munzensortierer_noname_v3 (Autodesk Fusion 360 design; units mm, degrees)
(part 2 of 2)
sketch "Skizze17" plane through (0, 0, 5.5) normal (0, 0, 1) x axis (1, 0, 0)
  line L1 (-47.8727, -14.1812) -> (-44.0075, -16.7301)
  line L2 (-31.8901, -15.0258) -> (-28.878, -11.5095)
  line L3 (33.1746, -11.9249) -> (28.5582, -12.2814)
  line L4 (43.8787, -23.8235) -> (42.948, -19.288)
  line L5 (-33.1746, 11.9249) -> (-28.5582, 12.2814)
  line L6 (-43.8787, 23.8235) -> (-42.948, 19.288)
  line L7 (11.9249, 33.1746) -> (12.2814, 28.5582)
  line L8 (23.8235, 43.8787) -> (19.288, 42.948)
  line L9 (-15.0258, 31.8901) -> (-11.5095, 28.878)
  line L10 (-14.1812, 47.8727) -> (-16.7301, 44.0075)
  line L11 (31.8901, 15.0258) -> (28.878, 11.5095)
  line L12 (47.8727, 14.1812) -> (44.0075, 16.7301)
  line L13 (15.0258, -31.8901) -> (11.5095, -28.878)
  line L14 (14.1812, -47.8727) -> (16.7301, -44.0075)
  line L15 (-23.8235, -43.8787) -> (-19.288, -42.948)
  line L16 (-11.9249, -33.1746) -> (-12.2814, -28.5582)
  arc A1 centre (-38.9151, -9.0081) radius 9.25 clockwise from (-31.8901, -15.0258) to (-44.0075, -16.7301)
  arc A2 centre (-39.8901, -2.0763) radius 14.5 clockwise from (-47.8727, -14.1812) to (-28.878, -11.5095)
  arc A3 centre (33.8868, -21.1475) radius 9.25 clockwise from (33.1746, -11.9249) to (42.948, -19.288)
  arc A4 centre (29.6747, -26.7384) radius 14.5 clockwise from (43.8787, -23.8235) to (28.5582, -12.2814)
  arc A5 centre (-29.6747, 26.7384) radius 14.5 clockwise from (-43.8787, 23.8235) to (-28.5582, 12.2814)
  arc A6 centre (-33.8868, 21.1475) radius 9.25 clockwise from (-33.1746, 11.9249) to (-42.948, 19.288)
  arc A7 centre (26.7384, 29.6747) radius 14.5 clockwise from (23.8235, 43.8787) to (12.2814, 28.5582)
  arc A8 centre (21.1475, 33.8868) radius 9.25 clockwise from (11.9249, 33.1746) to (19.288, 42.948)
  circle C1 centre (0, 0) radius 12.75
  arc A9 centre (0, 0) radius 59.0691 clockwise from (-58.9676, -3.4614) to (-59.0542, -1.3241)
  arc A10 centre (-58.8811, -4.7084) radius 1.25 clockwise from (-58.9676, -3.4614) to (-58.7683, -5.9533)
  arc A11 centre (0, 0) radius 59.0691 clockwise from (-58.5142, -8.0773) to (-58.7683, -5.9533)
  arc A12 centre (-58.3302, -9.3137) radius 1.25 clockwise from (-58.5142, -8.0773) to (-58.1201, -10.5459)
  arc A13 centre (0, 0) radius 59.0691 clockwise from (-57.7001, -12.6434) to (-58.1201, -10.5459)
  arc A14 centre (-57.4197, -13.8615) radius 1.25 clockwise from (-57.7001, -12.6434) to (-57.1135, -15.0734)
  arc A15 centre (0, 0) radius 59.0691 clockwise from (-56.5303, -17.1315) to (-57.1135, -15.0734)
  arc A16 centre (-56.1551, -18.3239) radius 1.25 clockwise from (-56.5303, -17.1315) to (-55.7548, -19.508)
  arc A17 centre (0, 0) radius 59.0691 clockwise from (-55.0119, -21.514) to (-55.7548, -19.508)
  arc A18 centre (-54.5443, -22.6732) radius 1.25 clockwise from (-55.0119, -21.514) to (-54.0523, -23.8224)
  arc A19 centre (0, 0) radius 59.0691 clockwise from (-53.1543, -25.7638) to (-54.0523, -23.8224)
  arc A20 centre (-52.5972, -26.8829) radius 1.25 clockwise from (-53.1543, -25.7638) to (-52.0166, -27.9898)
  arc A21 centre (0, 0) radius 59.0691 clockwise from (-50.9691, -29.8549) to (-52.0166, -27.9898)
  arc A22 centre (-50.3259, -30.9267) radius 1.25 clockwise from (-50.9691, -29.8549) to (-49.6602, -31.9847)
  arc A23 centre (0, 0) radius 59.0691 clockwise from (-48.4695, -33.7618) to (-49.6602, -31.9847)
  arc A24 centre (-47.7443, -34.7799) radius 1.25 clockwise from (-48.4695, -33.7618) to (-46.9976, -35.7824)
  arc A25 centre (0, 0) radius 59.0691 clockwise from (-45.6712, -37.4606) to (-46.9976, -35.7824)
  arc A26 centre (-44.8683, -38.4187) radius 1.25 clockwise from (-45.6712, -37.4606) to (-44.0453, -39.3595)
  arc A27 centre (0, 0) radius 59.0691 clockwise from (-42.5913, -40.9285) to (-44.0453, -39.3595)
  arc A28 centre (-41.7157, -41.8206) radius 1.25 clockwise from (-42.5913, -40.9285) to (-40.8214, -42.6939)
  arc A29 centre (0, 0) radius 59.0691 clockwise from (-39.2488, -44.144) to (-40.8214, -42.6939)
  arc A30 centre (-38.3059, -44.9646) radius 1.25 clockwise from (-39.2488, -44.144) to (-37.3458, -45.7651)
  arc A31 centre (0, 0) radius 59.0691 clockwise from (-35.6643, -47.0873) to (-37.3458, -45.7651)
  arc A32 centre (-34.6599, -47.8314) radius 1.25 clockwise from (-35.6643, -47.0873) to (-33.64, -48.5542)
  arc A33 centre (0, 0) radius 59.0691 clockwise from (-31.8599, -49.7403) to (-33.64, -48.5542)
  arc A34 centre (-30.8003, -50.4034) radius 1.25 clockwise from (-31.8599, -49.7403) to (-29.7268, -51.0438)
  arc A35 centre (0, 0) radius 59.0691 clockwise from (-27.8591, -52.0867) to (-29.7268, -51.0438)
  arc A36 centre (-26.7507, -52.6646) radius 1.25 clockwise from (-27.8591, -52.0867) to (-25.6303, -53.2188)
  arc A37 centre (0, 0) radius 59.0691 clockwise from (-23.6866, -54.112) to (-25.6303, -53.2188)
  arc A38 centre (-22.5362, -54.6011) radius 1.25 clockwise from (-23.6866, -54.112) to (-21.3758, -55.0657)
  arc A39 centre (0, 0) radius 59.0691 clockwise from (-19.368, -55.8036) to (-21.3758, -55.0657)
  arc A40 centre (-18.1828, -56.2009) radius 1.25 clockwise from (-19.368, -55.8036) to (-16.9895, -56.5731)
  arc A41 centre (0, 0) radius 59.0691 clockwise from (-14.93, -57.1511) to (-16.9895, -56.5731)
  arc A42 centre (-13.7173, -57.4543) radius 1.25 clockwise from (-14.93, -57.1511) to (-12.4985, -57.7317)
  arc A43 centre (0, 0) radius 59.0691 clockwise from (-10.3999, -58.1464) to (-12.4985, -57.7317)
  arc A44 centre (-9.1672, -58.3534) radius 1.25 clockwise from (-10.3999, -58.1464) to (-7.9304, -58.5343)
  arc A45 centre (0, 0) radius 59.0691 clockwise from (-5.8058, -58.7831) to (-7.9304, -58.5343)
  arc A46 centre (-4.5606, -58.8928) radius 1.25 clockwise from (-5.8058, -58.7831) to (-3.3134, -58.9761)
  arc A47 centre (0, 0) radius 59.0691 clockwise from (-1.1758, -59.0574) to (-3.3134, -58.9761)
  arc A48 centre (0.0741, -59.069) radius 1.25 clockwise from (-1.1758, -59.0574) to (1.3241, -59.0542)
  arc A49 centre (0, 0) radius 59.0691 clockwise from (3.4614, -58.9676) to (1.3241, -59.0542)
  arc A50 centre (4.7084, -58.8811) radius 1.25 clockwise from (3.4614, -58.9676) to (5.9533, -58.7683)
  arc A51 centre (0, 0) radius 59.0691 clockwise from (8.0773, -58.5142) to (5.9533, -58.7683)
  arc A52 centre (9.3137, -58.3302) radius 1.25 clockwise from (8.0773, -58.5142) to (10.5459, -58.1201)
  arc A53 centre (0, 0) radius 59.0691 clockwise from (12.6434, -57.7001) to (10.5459, -58.1201)
  arc A54 centre (13.8615, -57.4197) radius 1.25 clockwise from (12.6434, -57.7001) to (15.0734, -57.1135)
  arc A55 centre (0, 0) radius 59.0691 clockwise from (17.1315, -56.5303) to (15.0734, -57.1135)
  arc A56 centre (18.3239, -56.1551) radius 1.25 clockwise from (17.1315, -56.5303) to (19.508, -55.7548)
  arc A57 centre (0, 0) radius 59.0691 clockwise from (21.514, -55.0119) to (19.508, -55.7548)
  arc A58 centre (22.6732, -54.5443) radius 1.25 clockwise from (21.514, -55.0119) to (23.8224, -54.0523)
  arc A59 centre (0, 0) radius 59.0691 clockwise from (25.7638, -53.1543) to (23.8224, -54.0523)
  arc A60 centre (26.8829, -52.5972) radius 1.25 clockwise from (25.7638, -53.1543) to (27.9898, -52.0166)
  arc A61 centre (0, 0) radius 59.0691 clockwise from (29.8549, -50.9691) to (27.9898, -52.0166)
  arc A62 centre (30.9267, -50.3259) radius 1.25 clockwise from (29.8549, -50.9691) to (31.9847, -49.6602)
  arc A63 centre (0, 0) radius 59.0691 clockwise from (33.7618, -48.4695) to (31.9847, -49.6602)
  arc A64 centre (34.7799, -47.7443) radius 1.25 clockwise from (33.7618, -48.4695) to (35.7824, -46.9976)
  arc A65 centre (0, 0) radius 59.0691 clockwise from (37.4606, -45.6712) to (35.7824, -46.9976)
  arc A66 centre (38.4187, -44.8683) radius 1.25 clockwise from (37.4606, -45.6712) to (39.3595, -44.0453)
  arc A67 centre (0, 0) radius 59.0691 clockwise from (40.9285, -42.5913) to (39.3595, -44.0453)
  arc A68 centre (41.8206, -41.7157) radius 1.25 clockwise from (40.9285, -42.5913) to (42.6939, -40.8214)
  arc A69 centre (0, 0) radius 59.0691 clockwise from (44.144, -39.2488) to (42.6939, -40.8214)
  arc A70 centre (44.9646, -38.3059) radius 1.25 clockwise from (44.144, -39.2488) to (45.7651, -37.3458)
  arc A71 centre (0, 0) radius 59.0691 clockwise from (47.0873, -35.6643) to (45.7651, -37.3458)
  arc A72 centre (47.8314, -34.6599) radius 1.25 clockwise from (47.0873, -35.6643) to (48.5542, -33.64)
  arc A73 centre (0, 0) radius 59.0691 clockwise from (49.7403, -31.8599) to (48.5542, -33.64)
  arc A74 centre (50.4034, -30.8003) radius 1.25 clockwise from (49.7403, -31.8599) to (51.0438, -29.7268)
  arc A75 centre (0, 0) radius 59.0691 clockwise from (52.0867, -27.8591) to (51.0438, -29.7268)
  arc A76 centre (52.6646, -26.7507) radius 1.25 clockwise from (52.0867, -27.8591) to (53.2188, -25.6303)
  arc A77 centre (0, 0) radius 59.0691 clockwise from (54.112, -23.6866) to (53.2188, -25.6303)
  arc A78 centre (54.6011, -22.5362) radius 1.25 clockwise from (54.112, -23.6866) to (55.0657, -21.3758)
  arc A79 centre (0, 0) radius 59.0691 clockwise from (55.8036, -19.368) to (55.0657, -21.3758)
  arc A80 centre (56.2009, -18.1828) radius 1.25 clockwise from (55.8036, -19.368) to (56.5731, -16.9895)
  arc A81 centre (0, 0) radius 59.0691 clockwise from (57.1511, -14.93) to (56.5731, -16.9895)
  arc A82 centre (57.4543, -13.7173) radius 1.25 clockwise from (57.1511, -14.93) to (57.7317, -12.4985)
  arc A83 centre (0, 0) radius 59.0691 clockwise from (58.1464, -10.3999) to (57.7317, -12.4985)
  arc A84 centre (58.3534, -9.1672) radius 1.25 clockwise from (58.1464, -10.3999) to (58.5343, -7.9304)
  arc A85 centre (0, 0) radius 59.0691 clockwise from (58.7831, -5.8058) to (58.5343, -7.9304)
  arc A86 centre (58.8928, -4.5606) radius 1.25 clockwise from (58.7831, -5.8058) to (58.9761, -3.3134)
  arc A87 centre (0, 0) radius 59.0691 clockwise from (59.0574, -1.1758) to (58.9761, -3.3134)
  arc A88 centre (59.069, 0.0741) radius 1.25 clockwise from (59.0574, -1.1758) to (59.0542, 1.3241)
  arc A89 centre (0, 0) radius 59.0691 clockwise from (58.9676, 3.4614) to (59.0542, 1.3241)
  arc A90 centre (58.8811, 4.7084) radius 1.25 clockwise from (58.9676, 3.4614) to (58.7683, 5.9533)
  arc A91 centre (0, 0) radius 59.0691 clockwise from (58.5142, 8.0773) to (58.7683, 5.9533)
  arc A92 centre (58.3302, 9.3137) radius 1.25 clockwise from (58.5142, 8.0773) to (58.1201, 10.5459)
  arc A93 centre (0, 0) radius 59.0691 clockwise from (57.7001, 12.6434) to (58.1201, 10.5459)
  arc A94 centre (57.4197, 13.8615) radius 1.25 clockwise from (57.7001, 12.6434) to (57.1135, 15.0734)
  arc A95 centre (0, 0) radius 59.0691 clockwise from (56.5303, 17.1315) to (57.1135, 15.0734)
  arc A96 centre (56.1551, 18.3239) radius 1.25 clockwise from (56.5303, 17.1315) to (55.7548, 19.508)
  arc A97 centre (0, 0) radius 59.0691 clockwise from (55.0119, 21.514) to (55.7548, 19.508)
  arc A98 centre (54.5443, 22.6732) radius 1.25 clockwise from (55.0119, 21.514) to (54.0523, 23.8224)
  arc A99 centre (0, 0) radius 59.0691 clockwise from (53.1543, 25.7638) to (54.0523, 23.8224)
  arc A100 centre (52.5972, 26.8829) radius 1.25 clockwise from (53.1543, 25.7638) to (52.0166, 27.9898)
  arc A101 centre (0, 0) radius 59.0691 clockwise from (50.9691, 29.8549) to (52.0166, 27.9898)
  arc A102 centre (50.3259, 30.9267) radius 1.25 clockwise from (50.9691, 29.8549) to (49.6602, 31.9847)
  arc A103 centre (0, 0) radius 59.0691 clockwise from (48.4695, 33.7618) to (49.6602, 31.9847)
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  point P1 (0, 0)
  point P291 (0, 0)
  point P292 (0, 0)
  coincident P1 P291
  coincident P1 P292
extrude "Extrusion22" cut sketch "Skizze17" against normal blind 1
delete_face "Fläche löschen5"
delete_face "Fläche löschen6"
delete_face "Fläche löschen7"
delete_face "Fläche löschen8"
delete_face "Fläche löschen9"
delete_face "Fläche löschen10"
delete_face "Fläche löschen11"
delete_face "Fläche löschen12"
delete_face "Fläche löschen13"
delete_face "Fläche löschen14"
delete_face "Fläche löschen15"
delete_face "Fläche löschen16"
delete_face "Fläche löschen17"
delete_face "Fläche löschen18"
delete_face "Fläche löschen19"
delete_face "Fläche löschen20"
delete_face "Fläche löschen21"
sketch "Skizze18" plane through (0, 0, 65.6) normal (0, 0, 1) x axis (1, 0, 0)
  circle C1 centre (0, -39.9441) radius 32.1523
  circle C2 centre (0, -39.9441) radius 32.7523
extrude "Extrusion23" cut sketch "Skizze18" against normal blind 50
sketch "Skizze19" plane through (0, 0, 5.6) normal (0, 0, -1) x axis (-1, 0, 0)
  line L1 (8, -7) -> (12.9832, -7)
  line L2 (6, 6) -> (6, -5)
  line L3 (6.866, 6.5) -> (6, 6)
  line L4 (6.866, 7.5) -> (6.866, 6.5)
  line L5 (5.283, 10.1145) -> (6.3981, 8.7856)
  line L6 (4.4, 4.2486) -> (4.4, 9.7931)
  line L7 (3.1368, -5.4838) -> (3.2712, -4.9445)
  line L8 (-1.1962, -7) -> (1.1962, -7)
  line L9 (-3.2712, -4.9445) -> (-3.1368, -5.4838)
  line L10 (-4.4, 9.7931) -> (-4.4, 4.2486)
  line L11 (-6.3981, 8.7856) -> (-5.283, 10.1145)
  line L12 (-6.866, 6.5) -> (-6.866, 7.5)
  line L13 (-6, 6) -> (-6.866, 6.5)
  line L14 (-6, -5) -> (-6, 6)
  line L15 (-12.9832, -7) -> (-8, -7)
  line L16 (-14.75, 18.2945) -> (-14.75, 0)
  line L17 (-18.3545, -42.2598) -> (-23.3152, -2.9416)
  line L18 (23.3152, -2.9416) -> (18.3545, -42.2598)
  line L19 (14.75, 0) -> (14.75, 18.2945)
  line L20 (0, -39.9441) -> (7, -39.9441)
  line L21 (7, -25.6441) -> (0, -25.6441)
  line L22 (7, -54.2441) -> (0, -54.2441)
  circle C1 centre (0, -39.9441) radius 13.5
  arc A1 centre (8, -5) radius 2 clockwise from (8, -7) to (6, -5)
  arc A2 centre (4.866, 7.5) radius 2 clockwise from (6.3981, 8.7856) to (6.866, 7.5)
  arc A3 centre (4.9, 9.7931) radius 0.5 clockwise from (4.4, 9.7931) to (5.283, 10.1145)
  arc A4 centre (-33.6, 4.2486) radius 38 clockwise from (4.4, 4.2486) to (3.2712, -4.9445)
  arc A5 centre (1.1962, -5) radius 2 clockwise from (3.1368, -5.4838) to (1.1962, -7)
  arc A6 centre (-1.1962, -5) radius 2 clockwise from (-1.1962, -7) to (-3.1368, -5.4838)
  arc A7 centre (33.6, 4.2486) radius 38 clockwise from (-3.2712, -4.9445) to (-4.4, 4.2486)
  arc A8 centre (-4.9, 9.7931) radius 0.5 clockwise from (-5.283, 10.1145) to (-4.4, 9.7931)
  arc A9 centre (-4.866, 7.5) radius 2 clockwise from (-6.866, 7.5) to (-6.3981, 8.7856)
  arc A10 centre (-8, -5) radius 2 clockwise from (-6, -5) to (-8, -7)
  arc A11 centre (0, 0) radius 14.75 clockwise from (-12.9832, -7) to (-14.75, 0)
  arc A12 centre (0, 0) radius 23.5 clockwise from (-23.3152, -2.9416) to (-14.75, 18.2945)
  arc A13 centre (0, -39.9441) radius 18.5 clockwise from (-10.6945, -55.0397) to (-18.3545, -42.2598)
  arc A14 centre (0, 0) radius 56.0691 clockwise from (10.6945, -55.0397) to (-10.6945, -55.0397)
  arc A15 centre (0, -39.9441) radius 18.5 clockwise from (18.3545, -42.2598) to (10.6945, -55.0397)
  arc A16 centre (0, 0) radius 23.5 clockwise from (14.75, 18.2945) to (23.3152, -2.9416)
  arc A17 centre (0, 0) radius 14.75 clockwise from (14.75, 0) to (12.9832, -7)
  circle C2 centre (0, -39.9441) radius 14.3
  circle C3 centre (7, -39.9441) radius 14.3
  point P51 (7, -39.9441)
  point P52 (7, -39.9441)
  point P50 (0, -39.9441)
  point P53 (0, -39.9441)
  point P54 (0, -25.6441)
  point P55 (7, -25.6441)
  point P56 (0, -54.2441)
  point P57 (7, -54.2441)
  concentric C1 C2
  equal C2 C3
  coincident P51 P52
  coincident P50 P53
  horizontal L20
  coincident C2 P54
  coincident C3 P55
  tangent C3 L21
  coincident C2 P56
  coincident C3 P57
  parallel L21 L22
  tangent C3 L22
  tangent C2 L21
  dimension "d143" diameter C2 = 28.6 (= "27 mm + 1.6 mm")
  dimension "d145" distance P52 P53 = 7
extrude "Extrusion24" new body sketch "Skizze19" profile of C1 A15 L18 C2 C3 L21 L22 against normal blind 0.5 taper 60
extrude "Extrusion25" add of existing geometry blind 0.5 taper 50
extrude "Extrusion26" add of existing geometry blind 0.5 taper 45
sketch "Skizze25" plane through (0, 0, 5.6) normal (0, 0, -1) x axis (-1, 0, 0)
  line L1 (-6.0434, -26.9839) -> (43.9566, -3.6685)
  line L2 (43.9566, -76.2197) -> (43.9566, -3.6685)
  line L3 (-6.0434, -52.9043) -> (43.9566, -76.2197)
  line L4 (38, -39.9441) -> (0, -39.9441)
  line L5 (7, -54.2441) -> (0, -54.2441)
  line L6 (0, -25.6441) -> (7, -25.6441)
  arc A1 centre (7, -39.9441) radius 14.3 clockwise from (7, -25.6441) to (7, -54.2441)
  arc A2 centre (0, -39.9441) radius 14.3 clockwise from (0, -54.2441) to (0, -25.6441)
  point P6 (-6.0434, -26.9839)
  vertical L2
  horizontal L4
  dimension "d146" angle L1 L4 = 25
  dimension "d147" angle L3 L4 = 25
  dimension "d148" distance P6 L2 = 50
extrude "Extrusion29" sketch "Skizze25" profile of A1 L1 L2 L3 against normal blind 25
sketch "Skizze21" plane through (0, 0, 7.1) normal (0, 0, 1) x axis (1, 0, 0)
  line L1 (0, -35.3965) -> (0, -40.7441)
  line L2 (0, -17.7965) -> (0, -35.3965)
  line L3
  line L4 (6.0434, -52.9043) -> (-1.0371, -56.206)
  line L5 (-1.0371, -56.206) -> (-1.0371, -23.6822)
  line L6 (-1.0371, -56.206) -> (-7, -56.206)
  line L7 (-1.0371, -23.6822) -> (6.0434, -26.9839)
  line L8 (-7, -23.6822) -> (-1.0371, -23.6822)
  arc A1 centre (-7, -39.9441) radius 16.2619 clockwise from (-7, -56.206) to (-7, -23.6822)
  arc A2 centre (0, -39.9441) radius 14.3 clockwise from (6.0434, -26.9839) to (6.0434, -52.9043)
  point P7 (-1.0371, -56.206)
  point P10 (-1.0371, -56.206)
  point P13 (-1.0371, -23.6822)
  point P16 (-1.0371, -23.6822)
  point P6 (-7, -23.6822)
  point P15 (-7, -23.6822)
  vertical L1
  parallel L1 L2
  parallel L1 L3
  coincident P7 P10
  coincident P13 P16
  coincident P6 P15
work_point "Arbeitspunkt"
work_plane "Arbeitsebene" AlongDistance -39.944
sketch "Skizze22" plane through (0, -39.944, 0) normal (0, 1, 0) x axis (1, 0, 0)
  line L1 (-7.5, -7.966) -> (-7, -7.1)
  line L2 (-13.4841, -37.1) -> (-9.1429, -12.4798)
  line L3 (-23.2619, -7.1) -> (-7, -7.1)
  arc A1 centre (4.478, -14.8815) radius 13.831 clockwise from (-9.1429, -12.4798) to (-7.5, -7.966)
  point P2 (-7, -7.1)
  point P8 (-7, -7.1)
  point P3 (-7.5, -7.966)
  point P5 (-9.1429, -12.4798)
  point P7 (-13.4841, -37.1)
  point P9 (-23.2619, -7.1)
  tangent L1 A1
  tangent A1 L2
  coincident P2 P8
  dimension "d131" distance P2 P3 = 1
  dimension "d151" angle L1 L3 = 60
  dimension "d152" angle L2 L3 = 80
  dimension "d153" distance P5 P7 = 25
  dimension "d154" distance P7 P9 = 30
sweep "Sweeping" sketch "Skizze21" TwistAngle 0 TaperAngle 0
extrude "Extrusion27" add of existing geometry blind 30
sketch "Skizze23" plane through (0, 0, 0) normal (1, 0, 0) x axis (0, 0, -1)
sketch "Skizze24" plane through (0, -39.944, 0) normal (0, 1, 0) x axis (1, 0, 0)
  line L1 (6.0434, -37.1) -> (-1.0371, -37.1)
  line L2 (-21.3, -5.6) -> (-7, -5.6)
  line L3 (-23.2619, -7.1) -> (-22.7619, -6.6)
  line L4 (-22.7619, -6.6) -> (-22.166, -6.1)
  line L5 (14.3, -37.1) -> (6.0434, -37.1)
  line L6 (-7.5212, -37.1) -> (-3.18, -12.4798)
  line L7 (-7.5212, -37.1) -> (-13.4841, -37.1)
  line L8 (6.0434, -5.6) -> (14.3, -5.6)
  line L9 (0, -5.6) -> (6.0434, -5.6)
  line L10 (-7, -5.6) -> (0, -5.6)
  line L11 (14.3, -37.1) -> (14.3, -5.6)
  line L12 (-22.166, -6.1) -> (-21.3, -5.6)
  line L13 (-1.0371, -37.1) -> (-1.0371, -7.1)
  line L14 (-13.4841, -37.1) -> (-29.746, -37.1)
  line L15 (-1.5371, -7.966) -> (-1.0371, -7.1)
  line L16 (-29.746, -37.1) -> (-25.4048, -12.4798)
  curve K1 (-25.4048, -12.4798) -> (-23.7619, -7.966)
  line L17 (-23.7619, -7.966) -> (-23.2619, -7.1)
  line L18 (-1.0371, -37.1) -> (-7.5212, -37.1)
  arc A1 centre (10.4409, -14.8815) radius 13.831 clockwise from (-3.18, -12.4798) to (-1.5371, -7.966)
  point P12 (-7.5212, -37.1)
  point P22 (-7.5212, -37.1)
  point P2 (-1.0371, -37.1)
  point P23 (-1.0371, -37.1)
  coincident P12 P22
  coincident P2 P23
extrude "Extrusion28" add sketch "Skizze24" profile of L6 L13 A1 L15 L18 distance -16.262
copy_paste_bodies "Körper kopieren/einfügen"
shell "Schale" innerThickness 0.8
fillet "Abrundung5" radius 3
combine "Kombinieren4"
combine "Kombinieren5"
combine "Kombinieren7"
combine "Kombinieren6"
combine "Kombinieren3"
delete_face "Fläche löschen22"
delete_face "Fläche löschen23"
sketch "Skizze26" plane through (0, 0, 5.6) normal (0, 0, -1) x axis (-1, 0, 0)
  line L1 (0, -52.6441) -> (7, -52.6441)
  line L2 (7, -27.2441) -> (0, -27.2441)
  line L3 (23.3152, -2.9416) -> (19.6141, -32.2761)
  line L4 (14.75, 0) -> (14.75, 18.2945)
  line L5 (8, -7) -> (12.9832, -7)
  line L6 (6, 6) -> (6, -5)
  line L7 (6.866, 6.5) -> (6, 6)
  line L8 (6.866, 7.5) -> (6.866, 6.5)
  line L9 (5.283, 10.1145) -> (6.3981, 8.7856)
  line L10 (4.4, 4.2486) -> (4.4, 9.7931)
  line L11 (3.1368, -5.4838) -> (3.2712, -4.9445)
  line L12 (-1.1962, -7) -> (1.1962, -7)
  line L13 (-3.2712, -4.9445) -> (-3.1368, -5.4838)
  line L14 (-4.4, 9.7931) -> (-4.4, 4.2486)
  line L15 (-6.3981, 8.7856) -> (-5.283, 10.1145)
  line L16 (-6.866, 6.5) -> (-6.866, 7.5)
  line L17 (-6, 6) -> (-6.866, 6.5)
  line L18 (-6, -5) -> (-6, 6)
  line L19 (-12.9832, -7) -> (-8, -7)
  line L20 (-14.75, 18.2945) -> (-14.75, 0)
  line L21 (-18.3545, -42.2598) -> (-23.3152, -2.9416)
  line L22 (28.6352, 13.2785) -> (33.2516, 12.9219)
  line L23 (41.9684, 19.489) -> (42.8991, 24.0246)
  line L24 (-29.6375, 10.8589) -> (-32.6496, 14.3752)
  line L25 (-43.4569, 15.8953) -> (-47.3222, 13.3464)
  line L26 (10.8589, 29.6375) -> (14.3752, 32.6496)
  line L27 (15.8953, 43.4569) -> (13.3464, 47.3222)
  line L28 (-13.2785, 28.6352) -> (-12.9219, 33.2516)
  line L29 (-19.489, 41.9684) -> (-24.0246, 42.8991)
  line L30 (13.2785, -28.6352) -> (12.9219, -33.2516)
  line L31 (19.489, -41.9684) -> (24.0246, -42.8991)
  line L32 (-28.6352, -13.2785) -> (-33.2516, -12.9219)
  line L33 (-41.9684, -19.489) -> (-42.8991, -24.0246)
  line L34 (-10.8589, -29.6375) -> (-14.3752, -32.6496)
  line L35 (-15.8953, -43.4569) -> (-13.3464, -47.3222)
  line L36 (29.6375, -10.8589) -> (32.6496, -14.3752)
  line L37 (43.4569, -15.8953) -> (47.3222, -13.3464)
  line L38 (18.6764, -52.8671) -> (21.2007, -43.9757)
  curve K1 (-1.0265, -52.6025) -> (-5.3022, -51.3148)
  curve K2 (-5.3022, -28.5734) -> (-1.0265, -27.2856)
  arc A1 centre (7, -39.9441) radius 12.7 clockwise from (7, -27.2441) to (7, -52.6441)
  arc A2 centre (0, -39.9441) radius 12.7 clockwise from (0, -52.6441) to (-1.0265, -52.6025)
  arc A3 centre (0, -39.9441) radius 18.5 clockwise from (12.3812, -53.6902) to (10.6945, -55.0397)
  arc A4 centre (7, -39.9441) radius 14.7619 clockwise from (19.6141, -32.2761) to (12.3812, -53.6902)
  arc A5 centre (0, 0) radius 23.5 clockwise from (14.75, 18.2945) to (23.3152, -2.9416)
  arc A6 centre (0, 0) radius 14.75 clockwise from (14.75, 0) to (12.9832, -7)
  arc A7 centre (8, -5) radius 2 clockwise from (8, -7) to (6, -5)
  arc A8 centre (4.866, 7.5) radius 2 clockwise from (6.3981, 8.7856) to (6.866, 7.5)
  arc A9 centre (4.9, 9.7931) radius 0.5 clockwise from (4.4, 9.7931) to (5.283, 10.1145)
  arc A10 centre (-33.6, 4.2486) radius 38 clockwise from (4.4, 4.2486) to (3.2712, -4.9445)
  arc A11 centre (1.1962, -5) radius 2 clockwise from (3.1368, -5.4838) to (1.1962, -7)
  arc A12 centre (-1.1962, -5) radius 2 clockwise from (-1.1962, -7) to (-3.1368, -5.4838)
  arc A13 centre (33.6, 4.2486) radius 38 clockwise from (-3.2712, -4.9445) to (-4.4, 4.2486)
  arc A14 centre (-4.9, 9.7931) radius 0.5 clockwise from (-5.283, 10.1145) to (-4.4, 9.7931)
  arc A15 centre (-4.866, 7.5) radius 2 clockwise from (-6.866, 7.5) to (-6.3981, 8.7856)
  arc A16 centre (-8, -5) radius 2 clockwise from (-6, -5) to (-8, -7)
  arc A17 centre (0, 0) radius 14.75 clockwise from (-12.9832, -7) to (-14.75, 0)
  arc A18 centre (0, 0) radius 23.5 clockwise from (-23.3152, -2.9416) to (-14.75, 18.2945)
  arc A19 centre (0, -39.9441) radius 18.5 clockwise from (-10.6945, -55.0397) to (-18.3545, -42.2598)
  arc A20 centre (0, 0) radius 56.0691 clockwise from (10.6945, -55.0397) to (-10.6945, -55.0397)
  arc A21 centre (58.8811, -4.7084) radius 1.25 clockwise from (58.7683, -5.9533) to (58.9676, -3.4614)
  arc A22 centre (0, 0) radius 59.0691 clockwise from (59.0542, -1.3241) to (58.9676, -3.4614)
  arc A23 centre (59.069, -0.0741) radius 1.25 clockwise from (59.0542, -1.3241) to (59.0574, 1.1758)
  arc A24 centre (0, 0) radius 59.0691 clockwise from (58.9761, 3.3134) to (59.0574, 1.1758)
  arc A25 centre (58.8928, 4.5606) radius 1.25 clockwise from (58.9761, 3.3134) to (58.7831, 5.8058)
  arc A26 centre (0, 0) radius 59.0691 clockwise from (58.5343, 7.9304) to (58.7831, 5.8058)
  arc A27 centre (58.3534, 9.1672) radius 1.25 clockwise from (58.5343, 7.9304) to (58.1464, 10.3999)
  arc A28 centre (0, 0) radius 59.0691 clockwise from (57.7317, 12.4985) to (58.1464, 10.3999)
  arc A29 centre (57.4543, 13.7173) radius 1.25 clockwise from (57.7317, 12.4985) to (57.1511, 14.93)
  arc A30 centre (0, 0) radius 59.0691 clockwise from (56.5731, 16.9895) to (57.1511, 14.93)
  arc A31 centre (56.2009, 18.1828) radius 1.25 clockwise from (56.5731, 16.9895) to (55.8036, 19.368)
  arc A32 centre (0, 0) radius 59.0691 clockwise from (55.0657, 21.3758) to (55.8036, 19.368)
  arc A33 centre (54.6011, 22.5362) radius 1.25 clockwise from (55.0657, 21.3758) to (54.112, 23.6866)
  arc A34 centre (0, 0) radius 59.0691 clockwise from (53.2188, 25.6303) to (54.112, 23.6866)
  arc A35 centre (52.6646, 26.7507) radius 1.25 clockwise from (53.2188, 25.6303) to (52.0867, 27.8591)
  arc A36 centre (0, 0) radius 59.0691 clockwise from (51.0438, 29.7268) to (52.0867, 27.8591)
  arc A37 centre (50.4034, 30.8003) radius 1.25 clockwise from (51.0438, 29.7268) to (49.7403, 31.8599)
  arc A38 centre (0, 0) radius 59.0691 clockwise from (48.5542, 33.64) to (49.7403, 31.8599)
  arc A39 centre (47.8314, 34.6599) radius 1.25 clockwise from (48.5542, 33.64) to (47.0873, 35.6643)
  arc A40 centre (0, 0) radius 59.0691 clockwise from (45.7651, 37.3458) to (47.0873, 35.6643)
  arc A41 centre (44.9646, 38.3059) radius 1.25 clockwise from (45.7651, 37.3458) to (44.144, 39.2488)
  arc A42 centre (0, 0) radius 59.0691 clockwise from (42.6939, 40.8214) to (44.144, 39.2488)
  arc A43 centre (41.8206, 41.7157) radius 1.25 clockwise from (42.6939, 40.8214) to (40.9285, 42.5913)
  arc A44 centre (0, 0) radius 59.0691 clockwise from (39.3595, 44.0453) to (40.9285, 42.5913)
  arc A45 centre (38.4187, 44.8683) radius 1.25 clockwise from (39.3595, 44.0453) to (37.4606, 45.6712)
  arc A46 centre (0, 0) radius 59.0691 clockwise from (35.7824, 46.9976) to (37.4606, 45.6712)
  arc A47 centre (34.7799, 47.7443) radius 1.25 clockwise from (35.7824, 46.9976) to (33.7618, 48.4695)
  arc A48 centre (0, 0) radius 59.0691 clockwise from (31.9847, 49.6602) to (33.7618, 48.4695)
  arc A49 centre (30.9267, 50.3259) radius 1.25 clockwise from (31.9847, 49.6602) to (29.8549, 50.9691)
  arc A50 centre (0, 0) radius 59.0691 clockwise from (27.9898, 52.0166) to (29.8549, 50.9691)
  arc A51 centre (26.8829, 52.5972) radius 1.25 clockwise from (27.9898, 52.0166) to (25.7638, 53.1543)
  arc A52 centre (0, 0) radius 59.0691 clockwise from (23.8224, 54.0523) to (25.7638, 53.1543)
  arc A53 centre (22.6732, 54.5443) radius 1.25 clockwise from (23.8224, 54.0523) to (21.514, 55.0119)
  arc A54 centre (0, 0) radius 59.0691 clockwise from (19.508, 55.7548) to (21.514, 55.0119)
  arc A55 centre (18.3239, 56.1551) radius 1.25 clockwise from (19.508, 55.7548) to (17.1315, 56.5303)
  arc A56 centre (0, 0) radius 59.0691 clockwise from (15.0734, 57.1135) to (17.1315, 56.5303)
  arc A57 centre (13.8615, 57.4197) radius 1.25 clockwise from (15.0734, 57.1135) to (12.6434, 57.7001)
  arc A58 centre (0, 0) radius 59.0691 clockwise from (10.5459, 58.1201) to (12.6434, 57.7001)
  arc A59 centre (9.3137, 58.3302) radius 1.25 clockwise from (10.5459, 58.1201) to (8.0773, 58.5142)
  arc A60 centre (0, 0) radius 59.0691 clockwise from (5.9533, 58.7683) to (8.0773, 58.5142)
  arc A61 centre (4.7084, 58.8811) radius 1.25 clockwise from (5.9533, 58.7683) to (3.4614, 58.9676)
  arc A62 centre (0, 0) radius 59.0691 clockwise from (1.3241, 59.0542) to (3.4614, 58.9676)
  arc A63 centre (0.0741, 59.069) radius 1.25 clockwise from (1.3241, 59.0542) to (-1.1758, 59.0574)
  arc A64 centre (0, 0) radius 59.0691 clockwise from (-3.3134, 58.9761) to (-1.1758, 59.0574)
  arc A65 centre (-4.5606, 58.8928) radius 1.25 clockwise from (-3.3134, 58.9761) to (-5.8058, 58.7831)
  arc A66 centre (0, 0) radius 59.0691 clockwise from (-7.9304, 58.5343) to (-5.8058, 58.7831)
  arc A67 centre (-9.1672, 58.3534) radius 1.25 clockwise from (-7.9304, 58.5343) to (-10.3999, 58.1464)
  arc A68 centre (0, 0) radius 59.0691 clockwise from (-12.4985, 57.7317) to (-10.3999, 58.1464)
  arc A69 centre (-13.7173, 57.4543) radius 1.25 clockwise from (-12.4985, 57.7317) to (-14.93, 57.1511)
  arc A70 centre (0, 0) radius 59.0691 clockwise from (-16.9895, 56.5731) to (-14.93, 57.1511)
  arc A71 centre (-18.1828, 56.2009) radius 1.25 clockwise from (-16.9895, 56.5731) to (-19.368, 55.8036)
  arc A72 centre (0, 0) radius 59.0691 clockwise from (-21.3758, 55.0657) to (-19.368, 55.8036)
  arc A73 centre (-22.5362, 54.6011) radius 1.25 clockwise from (-21.3758, 55.0657) to (-23.6866, 54.112)
  arc A74 centre (0, 0) radius 59.0691 clockwise from (-25.6303, 53.2188) to (-23.6866, 54.112)
  arc A75 centre (-26.7507, 52.6646) radius 1.25 clockwise from (-25.6303, 53.2188) to (-27.8591, 52.0867)
  arc A76 centre (0, 0) radius 59.0691 clockwise from (-29.7268, 51.0438) to (-27.8591, 52.0867)
  arc A77 centre (-30.8003, 50.4034) radius 1.25 clockwise from (-29.7268, 51.0438) to (-31.8599, 49.7403)
  arc A78 centre (0, 0) radius 59.0691 clockwise from (-33.64, 48.5542) to (-31.8599, 49.7403)
  arc A79 centre (-34.6599, 47.8314) radius 1.25 clockwise from (-33.64, 48.5542) to (-35.6643, 47.0873)
  arc A80 centre (0, 0) radius 59.0691 clockwise from (-37.3458, 45.7651) to (-35.6643, 47.0873)
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  point P348 (21.2007, -43.9757)
  coincident A4 P348
  tangent A4 L38
extrude "Extrusion30" add sketch "Skizze26" to an object
fillet "Abrundung6" radius 1.25
copy_paste_bodies "Körper ausschneiden/einfügen8"
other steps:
step "Ё    Ā䛗    ܁    Ā䛙    ഁ    Ā䛚" bodies "drehscheibe"
base_feature "Basiselement1"
base_feature "Basiselement2"
base_feature "Basiselement3"
base_feature "Basiselement4"
base_feature "Basiselement5"
base_feature "Basiselement6"
base_feature "Basiselement7"
base_feature "Basiselement8"
base_feature "Basiselement1" bodies "Body"
base_feature "Basiselement2" bodies "Trichter"
base_feature "Basiselement3"
create_component "Komponente erstellen1"
remove_body "Körper entfernen1"
remove_body "Körper entfernen1"
remove_body "Körper entfernen2"
create_component "Komponente erstellen2"
remove_body "Körper entfernen2"
remove_body "Körper entfernen3"
remove_body "Körper entfernen4"
remove_body "Körper entfernen5"
remove_body "Körper entfernen6"
remove_body "Körper entfernen7"
remove_body "Körper entfernen8"
remove_body "Körper entfernen9"
named bodies: "drehscheibe", "Body", "Trichter"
